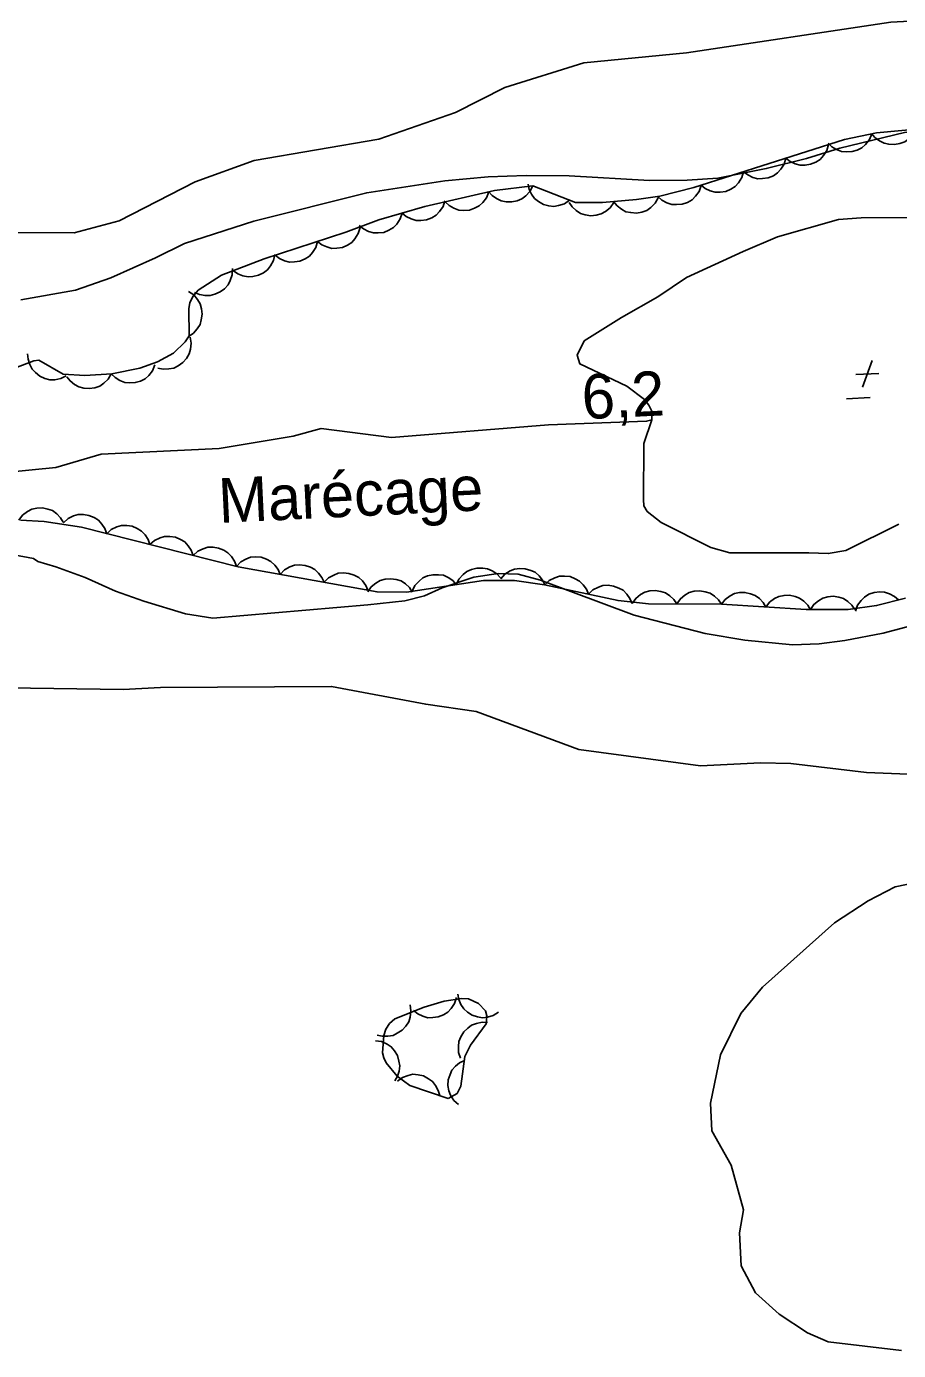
# Model space of a CAD drawing. Extents: x 336540 to 340074, y 5572036 to 5573747.
# Drawn here: x 336851.8 to 336910.5, y 5573059.3 to 5573148.4 of the extents above; entities that cross this region are included whole.
import ezdxf

# ---------------------------------------------------------------- set-up
doc = ezdxf.new("R2010")
doc.units = 0
for name, color, linetype in [('Niveau 2', 7, 'Continuous'), ('Niveau 3', 7, 'Continuous'), ('Niveau 4', 7, 'Continuous'), ('Niveau 44', 7, 'Continuous'), ('Niveau 7', 7, 'Continuous')]:
    doc.layers.add(name, color=color, linetype=linetype)

msp = doc.modelspace()

# ---------------------------------------------------------------- linework, layer by layer
at = {"layer": 'Niveau 2'}
for points in [[(336896.24, 5573146.62), (336910, 5573148.7), (336916.4, 5573149.03), (336918.59, 5573149.3), (336929.06, 5573149.83), (336931.9, 5573150.85), (336934.68, 5573152.53), (336940.87, 5573153.84), (336947.22, 5573155.54), (336958.63, 5573157.47), (336966.48, 5573159.75), (336970.33, 5573160.45), (336979.96, 5573160.78), (336983.31, 5573161.11), (336987.39, 5573160.98), (336992.17, 5573160.04), (336997.52, 5573158.28), (337003.28, 5573154.52)], [(336963.69, 5573147.82), (336961.68, 5573146.85), (336959, 5573145.86), (336957.57, 5573145.84), (336955.55, 5573146.07), (336953.97, 5573146.02), (336949.33, 5573145.14), (336946.32, 5573145.69), (336945.7, 5573145.53), (336943.22, 5573144.22), (336941.87, 5573144.08), (336937.13, 5573143.98), (336934.49, 5573143.75), (336928.71, 5573143.17), (336922.77, 5573142.36), (336920.01, 5573142.09), (336918.05, 5573142.06), (336913.5, 5573141.62), (336910.91, 5573141.26), (336906.57, 5573140.21), (336904.33, 5573139.53), (336901.61, 5573138.84), (336898.35, 5573138.2)], [(336849.63, 5573134.55), (336855.04, 5573134.52), (336858.06, 5573135.33), (336863.18, 5573137.96), (336867.14, 5573139.38), (336875.53, 5573140.81), (336880.69, 5573142.61), (336884.01, 5573144.3), (336889.33, 5573145.95), (336896.24, 5573146.62)], [(336898.35, 5573138.2), (336896.3, 5573138.06), (336893.75, 5573138.03), (336888.34, 5573138.36), (336885.46, 5573138.38), (336882.9, 5573138.29), (336879.97, 5573138.02), (336874.72, 5573137.21), (336867.13, 5573135.31), (336862.46, 5573133.79), (336860.5, 5573132.83), (336857.5, 5573131.5), (336855.11, 5573130.66), (336851.45, 5573130.02)], [(336850.97, 5573112.86), (336852.3, 5573112.6), (336852.58, 5573112.41), (336853.79, 5573112.06), (336855.76, 5573111.33), (336857.81, 5573110.41), (336859.73, 5573109.74), (336862.53, 5573108.88), (336864.37, 5573108.6), (336874.8, 5573109.5)], [(336874.8, 5573109.5), (336877.29, 5573109.77), (336878.6, 5573110.1), (336879.81, 5573110.64), (336881.94, 5573111.36), (336883.57, 5573111.6), (336884.92, 5573111.55), (336886.41, 5573111.15), (336892.72, 5573108.79), (336897.51, 5573107.56), (336900.18, 5573107.12), (336903.38, 5573106.8), (336905.17, 5573106.87), (336906.9, 5573107.1), (336909.48, 5573107.59), (336912.11, 5573108.28)], [(336966.1, 5573107.63), (336959.54, 5573106.97), (336951.25, 5573106.72), (336948.11, 5573105.52), (336946.63, 5573104.6), (336944.65, 5573103.65), (336941.27, 5573103.48), (336937.38, 5573103.62), (336929.19, 5573101.32), (336926.54, 5573100.16), (336923.87, 5573099.52), (336916.84, 5573098.13), (336913.96, 5573097.98), (336908.37, 5573098.22), (336903.27, 5573098.81), (336901.22, 5573098.87), (336897.18, 5573098.66), (336889, 5573099.77), (336882.09, 5573102.31), (336878.69, 5573102.81), (336872.36, 5573104), (336860.85, 5573103.93), (336858.33, 5573103.8), (336850.54, 5573103.9)], [(336914.64, 5573091.41), (336910.29, 5573090.53), (336908.48, 5573089.57), (336906.2, 5573088.1), (336901.35, 5573083.77), (336899.91, 5573082), (336898.53, 5573079.22), (336897.86, 5573075.97), (336897.96, 5573074.11), (336899.26, 5573071.8), (336900.08, 5573068.79), (336899.81, 5573067.25), (336899.93, 5573065.03), (336900.88, 5573063.22), (336902.48, 5573061.77), (336904.39, 5573060.53), (336905.79, 5573059.92), (336910.72, 5573059.33)]]:
    msp.add_lwpolyline(points, dxfattribs=at)
at = {"layer": 'Niveau 3'}
for p, q in [((336908.73, 5573125.94), (336908.08, 5573124.14)), ((336907.64, 5573124.98), (336909.2, 5573125.06)), ((336907.02, 5573123.35), (336908.61, 5573123.43))]:
    msp.add_line(p, q, dxfattribs=at)
at = {"layer": 'Niveau 4'}
for points in [[(336889.35, 5573127.26), (336891.87, 5573128.83), (336894.31, 5573130.21), (336896.25, 5573131.51), (336900.05, 5573133.27), (336902.37, 5573134.24), (336906.47, 5573135.41), (336908, 5573135.52), (336911.19, 5573135.54)], [(336910.53, 5573114.93), (336906.97, 5573113.14), (336905.78, 5573112.94), (336904.48, 5573113), (336899.17, 5573112.99), (336897.89, 5573113.35), (336894.53, 5573115.04), (336893.59, 5573115.78), (336893.38, 5573116.16), (336893.35, 5573116.57), (336893.38, 5573120.35), (336893.92, 5573121.94), (336893.9, 5573122.53), (336893.71, 5573122.93), (336893.42, 5573123.3), (336892.23, 5573124.21), (336889.07, 5573125.7), (336888.89, 5573126.28), (336889.35, 5573127.26)]]:
    msp.add_lwpolyline(points, dxfattribs=at)
at = {"layer": 'Niveau 44'}
for points in [[(336912.45, 5573141.56), (336909.03, 5573141.24), (336906.88, 5573140.79), (336896.73, 5573137.57), (336894.46, 5573136.99), (336892.88, 5573136.75), (336890.6, 5573136.56), (336888.77, 5573136.56), (336885.9, 5573137.67)], [(336908.71, 5573141.17), (336908.55, 5573140.79), (336908.29, 5573140.47), (336908.05, 5573140.24), (336907.74, 5573140.09), (336907.39, 5573139.98), (336907, 5573139.97), (336906.68, 5573139.99), (336906.35, 5573140.12), (336906.03, 5573140.31), (336905.77, 5573140.56)], [(336911.69, 5573141.49), (336911.49, 5573141.12), (336911.2, 5573140.84), (336910.93, 5573140.64), (336910.6, 5573140.52), (336910.24, 5573140.45), (336909.86, 5573140.48), (336909.54, 5573140.54), (336909.23, 5573140.71), (336908.93, 5573140.93), (336908.7, 5573141.21)], [(336905.8, 5573140.45), (336905.68, 5573140.05), (336905.46, 5573139.71), (336905.24, 5573139.46), (336904.95, 5573139.27), (336904.6, 5573139.13), (336904.23, 5573139.07), (336903.9, 5573139.06), (336903.56, 5573139.16), (336903.23, 5573139.32), (336902.94, 5573139.54)], [(336902.94, 5573139.54), (336902.82, 5573139.14), (336902.6, 5573138.8), (336902.38, 5573138.55), (336902.09, 5573138.36), (336901.75, 5573138.22), (336901.37, 5573138.17), (336901.04, 5573138.16), (336900.7, 5573138.25), (336900.37, 5573138.41), (336900.08, 5573138.63)], [(336900.08, 5573138.63), (336899.96, 5573138.23), (336899.74, 5573137.89), (336899.52, 5573137.64), (336899.23, 5573137.46), (336898.89, 5573137.31), (336898.51, 5573137.26), (336898.18, 5573137.25), (336897.84, 5573137.35), (336897.51, 5573137.5), (336897.22, 5573137.73)], [(336885.9, 5573137.67), (336883.33, 5573137.36), (336878.64, 5573136.29), (336875.54, 5573135.39), (336873.32, 5573134.56), (336867.82, 5573132.78), (336864.95, 5573131.66), (336863.37, 5573130.66), (336863.03, 5573130.26), (336862.82, 5573129.84), (336862.74, 5573129.4), (336862.76, 5573127.59), (336862.5, 5573127.18), (336861.72, 5573126.43), (336860.65, 5573125.83), (336859.45, 5573125.42), (336857.57, 5573125.04), (336855.75, 5573124.92), (336854.28, 5573125.02), (336852.65, 5573125.95), (336852.32, 5573125.91), (336851.09, 5573125.43)], [(336885.9, 5573137.67), (336885.71, 5573137.3), (336885.43, 5573137.01), (336885.17, 5573136.8), (336884.84, 5573136.67), (336884.48, 5573136.6), (336884.1, 5573136.61), (336883.77, 5573136.66), (336883.46, 5573136.82), (336883.16, 5573137.04), (336882.92, 5573137.31)], [(336888.37, 5573136.71), (336888.03, 5573136.47), (336887.64, 5573136.35), (336887.32, 5573136.29), (336886.97, 5573136.33), (336886.62, 5573136.43), (336886.29, 5573136.63), (336886.02, 5573136.82), (336885.82, 5573137.11), (336885.66, 5573137.44), (336885.58, 5573137.79)], [(336897.23, 5573137.7), (336897.09, 5573137.3), (336896.85, 5573136.98), (336896.62, 5573136.74), (336896.31, 5573136.57), (336895.96, 5573136.45), (336895.58, 5573136.42), (336895.25, 5573136.42), (336894.92, 5573136.54), (336894.59, 5573136.72), (336894.32, 5573136.96)], [(336879.98, 5573136.68), (336879.86, 5573136.28), (336879.62, 5573135.95), (336879.4, 5573135.7), (336879.1, 5573135.52), (336878.75, 5573135.39), (336878.37, 5573135.35), (336878.05, 5573135.34), (336877.71, 5573135.45), (336877.38, 5573135.61), (336877.1, 5573135.84)], [(336882.93, 5573137.27), (336882.78, 5573136.88), (336882.53, 5573136.56), (336882.29, 5573136.33), (336881.98, 5573136.17), (336881.63, 5573136.05), (336881.24, 5573136.03), (336880.92, 5573136.05), (336880.59, 5573136.17), (336880.27, 5573136.36), (336880, 5573136.6)], [(336894.33, 5573136.87), (336894.13, 5573136.51), (336893.84, 5573136.23), (336893.57, 5573136.03), (336893.24, 5573135.91), (336892.87, 5573135.85), (336892.49, 5573135.88), (336892.17, 5573135.94), (336891.86, 5573136.11), (336891.57, 5573136.34), (336891.34, 5573136.62)], [(336877.1, 5573135.84), (336876.97, 5573135.45), (336876.74, 5573135.11), (336876.52, 5573134.87), (336876.22, 5573134.69), (336875.87, 5573134.55), (336875.49, 5573134.51), (336875.17, 5573134.51), (336874.83, 5573134.61), (336874.5, 5573134.78), (336874.22, 5573135.01)], [(336891.35, 5573136.56), (336891.11, 5573136.21), (336890.8, 5573135.96), (336890.51, 5573135.79), (336890.17, 5573135.7), (336889.81, 5573135.66), (336889.43, 5573135.73), (336889.11, 5573135.82), (336888.82, 5573136.01), (336888.55, 5573136.26), (336888.35, 5573136.56)], [(336874.27, 5573134.87), (336874.15, 5573134.47), (336873.93, 5573134.12), (336873.72, 5573133.87), (336873.42, 5573133.68), (336873.08, 5573133.54), (336872.7, 5573133.48), (336872.37, 5573133.47), (336872.03, 5573133.57), (336871.7, 5573133.72), (336871.41, 5573133.94)], [(336868.54, 5573133.06), (336868.45, 5573132.66), (336868.25, 5573132.3), (336868.05, 5573132.04), (336867.77, 5573131.83), (336867.44, 5573131.67), (336867.06, 5573131.59), (336866.74, 5573131.56), (336866.39, 5573131.63), (336866.05, 5573131.77), (336865.75, 5573131.97)], [(336871.41, 5573133.94), (336871.3, 5573133.54), (336871.08, 5573133.2), (336870.86, 5573132.95), (336870.57, 5573132.76), (336870.23, 5573132.62), (336869.85, 5573132.56), (336869.52, 5573132.55), (336869.18, 5573132.64), (336868.84, 5573132.8), (336868.56, 5573133.02)], [(336865.68, 5573132.12), (336865.66, 5573131.7), (336865.53, 5573131.32), (336865.39, 5573131.02), (336865.15, 5573130.76), (336864.85, 5573130.54), (336864.5, 5573130.39), (336864.19, 5573130.3), (336863.84, 5573130.3), (336863.47, 5573130.37), (336863.14, 5573130.51)], [(336862.73, 5573130.57), (336863.08, 5573130.34), (336863.34, 5573130.03), (336863.51, 5573129.75), (336863.6, 5573129.41), (336863.64, 5573129.04), (336863.58, 5573128.66), (336863.5, 5573128.35), (336863.3, 5573128.05), (336863.06, 5573127.78), (336862.76, 5573127.57)], [(336862.84, 5573127.5), (336862.91, 5573127.09), (336862.86, 5573126.69), (336862.77, 5573126.37), (336862.59, 5573126.07), (336862.35, 5573125.79), (336862.03, 5573125.57), (336861.74, 5573125.42), (336861.4, 5573125.36), (336861.03, 5573125.35), (336860.67, 5573125.42)], [(336854.5, 5573124.89), (336854.13, 5573124.71), (336853.73, 5573124.64), (336853.4, 5573124.63), (336853.06, 5573124.72), (336852.72, 5573124.88), (336852.43, 5573125.12), (336852.2, 5573125.35), (336852.04, 5573125.67), (336851.93, 5573126.02), (336851.9, 5573126.38)], [(336860.47, 5573125.63), (336860.31, 5573125.24), (336860.05, 5573124.93), (336859.81, 5573124.7), (336859.49, 5573124.55), (336859.14, 5573124.44), (336858.76, 5573124.43), (336858.43, 5573124.46), (336858.11, 5573124.59), (336857.79, 5573124.78), (336857.53, 5573125.03)], [(336857.53, 5573125.04), (336857.32, 5573124.68), (336857.02, 5573124.4), (336856.75, 5573124.21), (336856.42, 5573124.1), (336856.05, 5573124.04), (336855.67, 5573124.08), (336855.35, 5573124.15), (336855.05, 5573124.32), (336854.76, 5573124.56), (336854.54, 5573124.84)], [(336851.31, 5573115.2), (336851.56, 5573115.53), (336851.89, 5573115.77), (336852.18, 5573115.93), (336852.52, 5573116), (336852.89, 5573116.01), (336853.26, 5573115.93), (336853.57, 5573115.83), (336853.86, 5573115.62), (336854.12, 5573115.35), (336854.3, 5573115.05)], [(336854.31, 5573115.02), (336854.62, 5573115.3), (336854.99, 5573115.47), (336855.31, 5573115.56), (336855.66, 5573115.57), (336856.02, 5573115.51), (336856.37, 5573115.36), (336856.66, 5573115.19), (336856.89, 5573114.93), (336857.1, 5573114.62), (336857.22, 5573114.28)], [(336851.42, 5573115.19), (336853.02, 5573115.11), (336855.53, 5573114.71), (336866.06, 5573112.06), (336875.42, 5573110.36), (336877.4, 5573110.35), (336882.58, 5573111.13), (336884.67, 5573111.12), (336886.68, 5573110.84), (336891.64, 5573109.78), (336893.69, 5573109.57), (336898.61, 5573109.53), (336904.29, 5573109.17), (336907.13, 5573109.17), (336909.04, 5573109.44), (336910.99, 5573109.95)], [(336857.22, 5573114.28), (336857.53, 5573114.56), (336857.9, 5573114.73), (336858.22, 5573114.83), (336858.57, 5573114.84), (336858.93, 5573114.78), (336859.28, 5573114.62), (336859.57, 5573114.46), (336859.8, 5573114.2), (336860.01, 5573113.89), (336860.13, 5573113.55)], [(336860.13, 5573113.55), (336860.44, 5573113.83), (336860.81, 5573114), (336861.12, 5573114.1), (336861.48, 5573114.1), (336861.84, 5573114.05), (336862.19, 5573113.89), (336862.47, 5573113.73), (336862.71, 5573113.47), (336862.91, 5573113.16), (336863.04, 5573112.82)], [(336863.04, 5573112.82), (336863.35, 5573113.1), (336863.72, 5573113.27), (336864.03, 5573113.37), (336864.39, 5573113.37), (336864.75, 5573113.31), (336865.1, 5573113.16), (336865.38, 5573113), (336865.62, 5573112.74), (336865.82, 5573112.43), (336865.95, 5573112.09)], [(336865.95, 5573112.08), (336866.24, 5573112.38), (336866.59, 5573112.57), (336866.9, 5573112.69), (336867.25, 5573112.72), (336867.62, 5573112.69), (336867.98, 5573112.56), (336868.27, 5573112.41), (336868.53, 5573112.17), (336868.75, 5573111.87), (336868.9, 5573111.54)], [(336868.9, 5573111.54), (336869.19, 5573111.84), (336869.55, 5573112.04), (336869.85, 5573112.16), (336870.2, 5573112.19), (336870.57, 5573112.15), (336870.93, 5573112.02), (336871.23, 5573111.88), (336871.48, 5573111.63), (336871.7, 5573111.34), (336871.85, 5573111.01)], [(336880.75, 5573110.85), (336880.93, 5573111.23), (336881.21, 5573111.53), (336881.46, 5573111.74), (336881.78, 5573111.88), (336882.14, 5573111.97), (336882.53, 5573111.96), (336882.85, 5573111.92), (336883.17, 5573111.77), (336883.48, 5573111.57), (336883.72, 5573111.3)], [(336883.74, 5573111.25), (336884.02, 5573111.56), (336884.37, 5573111.77), (336884.67, 5573111.9), (336885.02, 5573111.94), (336885.39, 5573111.92), (336885.76, 5573111.81), (336886.05, 5573111.68), (336886.32, 5573111.45), (336886.55, 5573111.16), (336886.71, 5573110.84)], [(336871.85, 5573111.01), (336872.14, 5573111.31), (336872.5, 5573111.5), (336872.81, 5573111.62), (336873.16, 5573111.65), (336873.52, 5573111.61), (336873.88, 5573111.48), (336874.18, 5573111.34), (336874.43, 5573111.1), (336874.66, 5573110.8), (336874.8, 5573110.47)], [(336874.79, 5573110.36), (336875.03, 5573110.71), (336875.34, 5573110.96), (336875.63, 5573111.13), (336875.97, 5573111.22), (336876.34, 5573111.25), (336876.71, 5573111.19), (336877.03, 5573111.1), (336877.32, 5573110.9), (336877.59, 5573110.65), (336877.79, 5573110.35)], [(336877.79, 5573110.41), (336877.97, 5573110.79), (336878.24, 5573111.09), (336878.49, 5573111.3), (336878.82, 5573111.44), (336879.18, 5573111.52), (336879.56, 5573111.52), (336879.88, 5573111.48), (336880.2, 5573111.33), (336880.51, 5573111.12), (336880.75, 5573110.85)], [(336886.71, 5573110.83), (336887.01, 5573111.12), (336887.38, 5573111.31), (336887.69, 5573111.42), (336888.04, 5573111.43), (336888.41, 5573111.39), (336888.76, 5573111.25), (336889.05, 5573111.09), (336889.3, 5573110.84), (336889.51, 5573110.54), (336889.65, 5573110.21)], [(336889.65, 5573110.21), (336889.95, 5573110.5), (336890.31, 5573110.68), (336890.62, 5573110.79), (336890.97, 5573110.81), (336891.34, 5573110.76), (336891.7, 5573110.62), (336891.98, 5573110.47), (336892.23, 5573110.22), (336892.44, 5573109.91), (336892.58, 5573109.58)], [(336892.59, 5573109.58), (336892.83, 5573109.92), (336893.14, 5573110.18), (336893.43, 5573110.35), (336893.77, 5573110.43), (336894.14, 5573110.46), (336894.51, 5573110.4), (336894.83, 5573110.3), (336895.12, 5573110.11), (336895.39, 5573109.85), (336895.59, 5573109.55)], [(336895.59, 5573109.55), (336895.83, 5573109.9), (336896.14, 5573110.15), (336896.43, 5573110.32), (336896.77, 5573110.41), (336897.14, 5573110.44), (336897.51, 5573110.37), (336897.83, 5573110.28), (336898.12, 5573110.08), (336898.39, 5573109.83), (336898.59, 5573109.53)], [(336898.59, 5573109.53), (336898.85, 5573109.86), (336899.18, 5573110.1), (336899.47, 5573110.25), (336899.81, 5573110.32), (336900.18, 5573110.33), (336900.56, 5573110.24), (336900.86, 5573110.13), (336901.15, 5573109.92), (336901.4, 5573109.65), (336901.58, 5573109.34)], [(336901.58, 5573109.34), (336901.84, 5573109.67), (336902.17, 5573109.91), (336902.46, 5573110.06), (336902.81, 5573110.13), (336903.18, 5573110.14), (336903.55, 5573110.05), (336903.86, 5573109.94), (336904.14, 5573109.73), (336904.4, 5573109.46), (336904.58, 5573109.15)], [(336904.58, 5573109.17), (336904.81, 5573109.52), (336905.13, 5573109.77), (336905.41, 5573109.94), (336905.75, 5573110.03), (336906.12, 5573110.07), (336906.5, 5573110), (336906.81, 5573109.91), (336907.1, 5573109.72), (336907.38, 5573109.47), (336907.58, 5573109.17)], [(336907.61, 5573109.07), (336907.75, 5573109.46), (336907.99, 5573109.79), (336908.22, 5573110.02), (336908.52, 5573110.2), (336908.87, 5573110.32), (336909.25, 5573110.36), (336909.58, 5573110.35), (336909.91, 5573110.24), (336910.24, 5573110.06), (336910.51, 5573109.82)], [(336883.59, 5573082.09), (336883.24, 5573081.87), (336882.84, 5573081.76), (336882.52, 5573081.72), (336882.17, 5573081.77), (336881.82, 5573081.89), (336881.5, 5573082.1), (336881.25, 5573082.31), (336881.06, 5573082.61), (336880.91, 5573082.95), (336880.85, 5573083.3)], [(336877.64, 5573082.58), (336877.7, 5573082.17), (336877.64, 5573081.76), (336877.55, 5573081.45), (336877.36, 5573081.15), (336877.11, 5573080.88), (336876.78, 5573080.67), (336876.49, 5573080.52), (336876.14, 5573080.47), (336875.77, 5573080.47), (336875.42, 5573080.55)], [(336880.2, 5573076.29), (336880.81, 5573076.63), (336881.06, 5573077.11), (336881.33, 5573079.11), (336881.71, 5573079.88), (336882.77, 5573081.3), (336882.8, 5573081.85), (336882.72, 5573082.18), (336882.25, 5573082.68), (336881.57, 5573082.98), (336881.13, 5573083.01), (336879.94, 5573082.83), (336878.58, 5573082.42), (336876.61, 5573081.64), (336876.26, 5573081.32), (336876.01, 5573080.94), (336875.87, 5573080.53), (336875.79, 5573079.35), (336875.87, 5573079.01), (336876.03, 5573078.68), (336876.76, 5573077.79), (336877.62, 5573077.16), (336880.2, 5573076.29)], [(336880.76, 5573083.08), (336880.63, 5573082.68), (336880.4, 5573082.34), (336880.18, 5573082.09), (336879.88, 5573081.91), (336879.54, 5573081.77), (336879.16, 5573081.73), (336878.83, 5573081.72), (336878.5, 5573081.82), (336878.16, 5573081.98), (336877.88, 5573082.21)], [(336881.04, 5573078.99), (336880.9, 5573079.38), (336880.89, 5573079.79), (336880.92, 5573080.12), (336881.05, 5573080.44), (336881.25, 5573080.76), (336881.52, 5573081.02), (336881.78, 5573081.22), (336882.11, 5573081.34), (336882.48, 5573081.41), (336882.84, 5573081.39)], [(336875.31, 5573080.17), (336875.72, 5573080.11), (336876.09, 5573079.94), (336876.37, 5573079.76), (336876.6, 5573079.49), (336876.79, 5573079.17), (336876.89, 5573078.8), (336876.95, 5573078.48), (336876.91, 5573078.13), (336876.8, 5573077.78), (336876.62, 5573077.47)], [(336880.89, 5573075.88), (336880.58, 5573076.16), (336880.37, 5573076.51), (336880.24, 5573076.81), (336880.19, 5573077.16), (336880.21, 5573077.53), (336880.33, 5573077.89), (336880.46, 5573078.19), (336880.69, 5573078.46), (336880.97, 5573078.69), (336881.3, 5573078.85)], [(336876.8, 5573077.44), (336877.13, 5573077.69), (336877.51, 5573077.83), (336877.83, 5573077.91), (336878.18, 5573077.88), (336878.54, 5573077.8), (336878.88, 5573077.61), (336879.15, 5573077.43), (336879.36, 5573077.15), (336879.54, 5573076.83), (336879.64, 5573076.48)]]:
    msp.add_lwpolyline(points, dxfattribs=at)
at = {"layer": 'Niveau 7'}
msp.add_lwpolyline([(336841.97, 5573118.4), (336842.48, 5573118.51), (336845.91, 5573119.02), (336848.19, 5573118.63), (336850.38, 5573118.4), (336853.79, 5573118.74), (336856.85, 5573119.64), (336864.78, 5573120.02), (336869.76, 5573120.85), (336871.66, 5573121.36), (336876.38, 5573120.75), (336886.96, 5573121.6), (336893.56, 5573121.84), (336893.92, 5573121.94)], dxfattribs=at)

# ---------------------------------------------------------------- texts
at = {"layer": 'Niveau 3'}
msp.add_text('    6,2 ', height=3, rotation=2.7712, dxfattribs=at).set_placement((336884.81, 5573121.76))
at = {"layer": 'Niveau 7'}
msp.add_text('Marécage', height=3, rotation=2.77808, dxfattribs=at).set_placement((336864.8, 5573115))

doc.saveas('drawing.dxf')
